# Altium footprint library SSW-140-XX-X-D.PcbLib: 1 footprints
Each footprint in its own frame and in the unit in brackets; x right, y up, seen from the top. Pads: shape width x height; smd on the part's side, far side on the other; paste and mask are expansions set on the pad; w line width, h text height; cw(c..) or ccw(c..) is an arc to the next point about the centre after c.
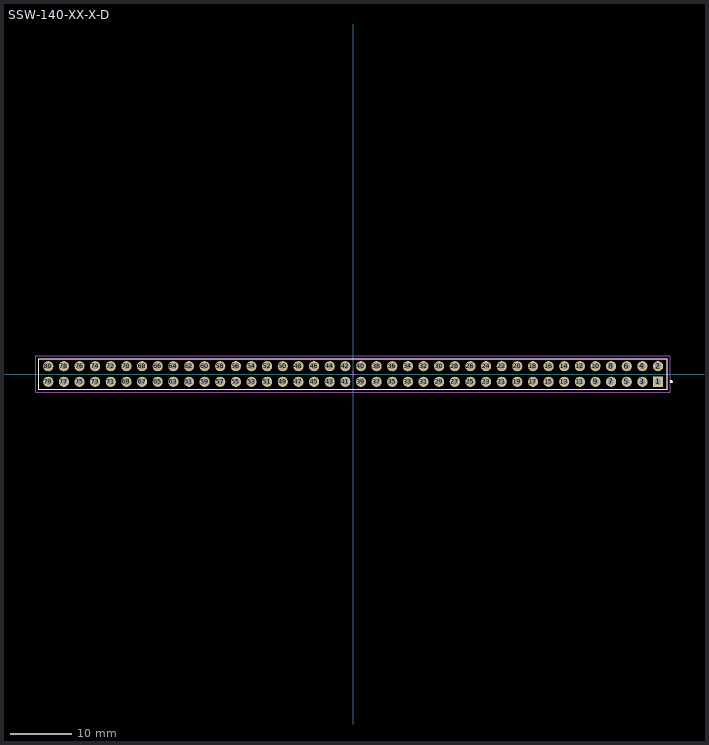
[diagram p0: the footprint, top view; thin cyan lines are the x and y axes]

## SSW-140-XX-X-D [mm] "2.54mm pitch, 80 pin, socket strip; double row"
height 8.51
pads (80):
  rect 1.65x1.65 / inner round 1.65 / far side rect 1.65x1.65 hole 1 mask+0: 1(49.53,-1.27)
  round 1.65 hole 1 mask+0: 2(49.53,1.27) 3(46.99,-1.27) 4(46.99,1.27) 5(44.45,-1.27) 6(44.45,1.27) 7(41.91,-1.27) 8(41.91,1.27) 9(39.37,-1.27) 10(39.37,1.27) 11(36.83,-1.27) 12(36.83,1.27) 13(34.29,-1.27) 14(34.29,1.27) 15(31.75,-1.27) 16(31.75,1.27) 17(29.21,-1.27) 18(29.21,1.27) 19(26.67,-1.27) 20(26.67,1.27) 21(24.13,-1.27) 22(24.13,1.27) 23(21.59,-1.27) 24(21.59,1.27) 25(19.05,-1.27) 26(19.05,1.27) 27(16.51,-1.27) 28(16.51,1.27) 29(13.97,-1.27) 30(13.97,1.27) 31(11.43,-1.27) 32(11.43,1.27) 33(8.89,-1.27) 34(8.89,1.27) 35(6.35,-1.27) 36(6.35,1.27) 37(3.81,-1.27) 38(3.81,1.27) 39(1.27,-1.27) 40(1.27,1.27) 41(-1.27,-1.27) 42(-1.27,1.27) 43(-3.81,-1.27) 44(-3.81,1.27) 45(-6.35,-1.27) 46(-6.35,1.27) 47(-8.89,-1.27) 48(-8.89,1.27) 49(-11.43,-1.27) 50(-11.43,1.27) 51(-13.97,-1.27) 52(-13.97,1.27) 53(-16.51,-1.27) 54(-16.51,1.27) 55(-19.05,-1.27) 56(-19.05,1.27) 57(-21.59,-1.27) 58(-21.59,1.27) 59(-24.13,-1.27) 60(-24.13,1.27) 61(-26.67,-1.27) 62(-26.67,1.27) 63(-29.21,-1.27) 64(-29.21,1.27) 65(-31.75,-1.27) 66(-31.75,1.27) 67(-34.29,-1.27) 68(-34.29,1.27) 69(-36.83,-1.27) 70(-36.83,1.27) 71(-39.37,-1.27) 72(-39.37,1.27) 73(-41.91,-1.27) 74(-41.91,1.27) 75(-44.45,-1.27) 76(-44.45,1.27) 77(-46.99,-1.27) 78(-46.99,1.27) 79(-49.53,-1.27) 80(-49.53,1.27)
Top Overlay:
  circle w0.25: c51.7,-1.25 r0.125
  lines w0.2: -51.05,-2.5 -51.05,2.5 51.05,2.5 51.05,-2.5 -51.05,-2.5
Mechanical 12:
  lines w0.001: -51.05,-2.5 -51.05,2.5 51.05,2.5 51.05,-2.5 -51.05,-2.5
Mechanical 13:
  lines w0.1: -51.05,-2.5 -51.05,2.5 51.05,2.5 51.05,-2.5 -51.05,-2.5
  text ".Designator" at 0.127,-0.127 h1.52
Mechanical 15:
  lines w0.05: -0.5,0 0.5,0 ; 0,-0.5 0,0.5 ; -51.55,-3 -51.55,3 51.55,3 51.55,-3 -51.55,-3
